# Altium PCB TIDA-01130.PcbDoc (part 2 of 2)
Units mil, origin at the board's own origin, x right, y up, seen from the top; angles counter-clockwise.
Board outline 1055.12 x 1877.5 mil, 6 copper layers (Layer 1 - Top Layer, Layer 2 - GND, Layer 3 - Signal, Layer 4 - Signal, Layer 5 - PWR, Layer 6 - Bottom Layer), stack 66.234 mil thick; 91 components, 54 nets, 295 pads, 113 vias.
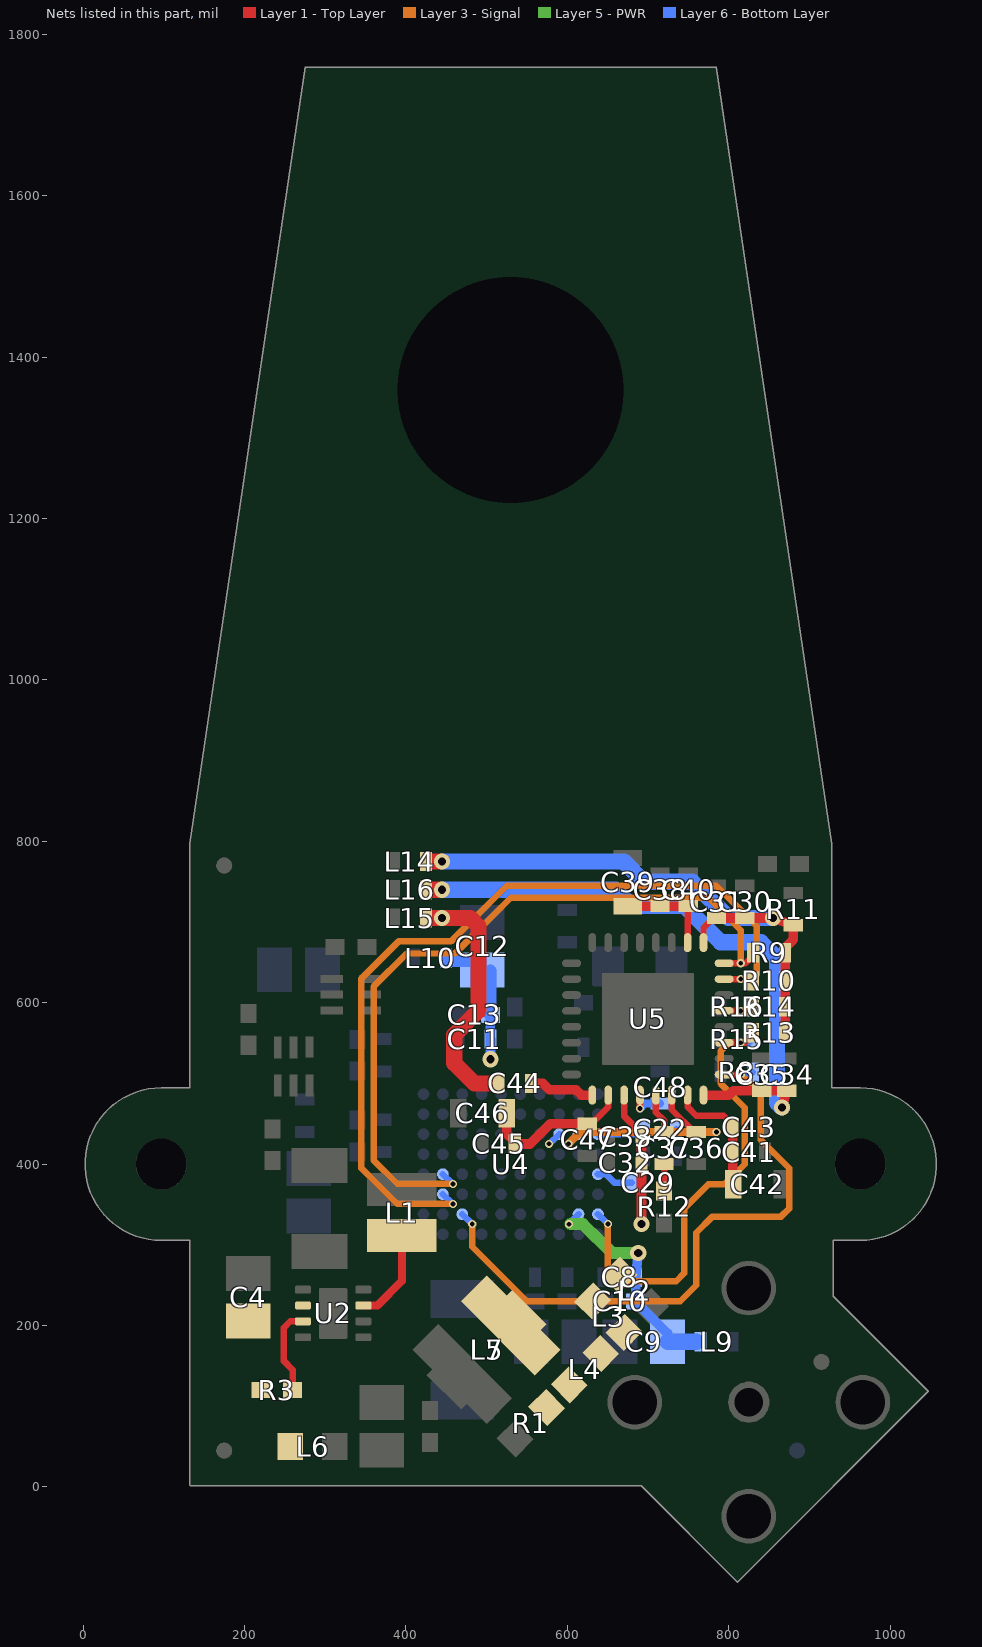
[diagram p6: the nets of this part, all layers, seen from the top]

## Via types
v1: diameter 10, hole 6, Layer 1 - Top Layer to Layer 6 - Bottom Layer, tented both sides, 56 vias
v2: diameter 20, hole 10, Layer 1 - Top Layer to Layer 6 - Bottom Layer, tented both sides, 50 vias
v3: diameter 19.68, hole 7.87, Layer 1 - Top Layer to Layer 6 - Bottom Layer, tented both sides, 7 vias

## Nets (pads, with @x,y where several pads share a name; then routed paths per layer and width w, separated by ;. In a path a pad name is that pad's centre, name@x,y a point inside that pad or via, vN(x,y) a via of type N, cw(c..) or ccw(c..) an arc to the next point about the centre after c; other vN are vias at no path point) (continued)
NetC22_1: C22.1 U4.C1 | length 59.3
  Layer 6 - Bottom Layer w8: U4.C1@638.07,437.2 689.2,437.2 C22.1@695,443
NetC22_2: C22.2 U4.C2 | length 258.1
  Layer 3 - Signal w10: v1(601.65,425.2) 616.46,440 v1(785,440)
  Layer 6 - Bottom Layer w8: v1(601.65,425.2) 602.05,425.2 U4.C2@614.06,437.2 ; C22.2@735,443 738,440 v1(785,440)
NetC29_1: C29.1 U4.E1 | length 46.3
  Layer 6 - Bottom Layer w8: U4.E1@638.07,387.6 648,387.6 658.6,377 C29.1@680,377
NetC36_2: C36.2 U5.14 | length 59.9
  Layer 1 - Top Layer w8: U5.14@729.53,485.51 729.53,467.47 757,440 C36.2@760,440
NetC37_1: C37.1 R12.2 | length 30.3
  Layer 1 - Top Layer w8: R12.2@720,369.69 C37.1@720,400
NetC37_2: C37.2 U5.13 | length 49.7
  Layer 1 - Top Layer w8: U5.13@709.84,485.51 709.84,464.16 720,454 C37.2@720,440
NetC44_2: C44.2 U5.9 | length 75
  Layer 1 - Top Layer w12: C44.2@560,500 570,500 578,492 611,492 617.49,485.51 U5.9@629,485.51
NetC48_1: C48.1 U5.12 | length 43.8
  Layer 1 - Top Layer w8: v1(690.16,469) U5.12@690.16,485.51
  Layer 6 - Bottom Layer w10: v1(690.16,469) 696.16,475 C48.1@715,475
NetL1_1: L1.1 U2.7 | length 116.6
  Layer 1 - Top Layer w10: U2.7@347.4,224.84 364.84,224.84 395.04,255.04 L1.1@395.04,311.46
NetL2_2: L2.2 L3.1
NetL3_2: L3.2 L4.1
NetL4_2: L4.2 L5.2 L7.1 R1.2
NetR3_1: R3.1 U2.3 | length 108.6
  Layer 1 - Top Layer w8: R3.1@259.68,120 259.68,145.32 249,156 249,197.31 256.84,205.16 U2.3@272.6,205.16
NetR14_1: R14.1 R16.2 U5.21 | length 54.8
  Layer 1 - Top Layer w8: U5.21@794.49,589.84 v1(815,589.84) 824.84,589.84 R14.1@830,595
  Layer 6 - Bottom Layer w8: v1(815,589.84) 824.84,589.84 R16.2@830,595
PVDD: C8.1 C9.1 C10.1 L9.2 U4.G2 | length 278.1
  Layer 5 - PWR w15: v1@604,325.59 619.41,325.59 656,290 v2(688,290)
  Layer 6 - Bottom Layer w8: v1(602.05,325.59) 602.05,325.98 U4.G2@614.06,337.99
  Layer 6 - Bottom Layer w12: v2(688,290) C8.1@685,260 685,230.32 C10.1@684.68,230 724.53,190.16 C9.1@724.53,180
  Layer 6 - Bottom Layer w20: C9.1@724.53,180 L9.2@760,180
SCL: R9.1 U4.E9 U5.24 | length 944.1
  Layer 1 - Top Layer w8: U5.24@794.49,648.9 v1(815,648.9) 820.9,648.9 830,658 R9.1@830,662
  Layer 3 - Signal w8: v1@458.07,375.59 389.41,375.59 360,405 360,620 401,661 461,661 530,730 775,730 815,690 v1(815,648.9)
  Layer 6 - Bottom Layer w8: U4.E9@445.94,387.6 457.95,375.59 v1(458.35,375.59)
SDA: R10.1 U4.F9 U5.23 | length 1060.6
  Layer 1 - Top Layer w8: U5.23@794.49,629.21 v1(815,629.21) 829.21,629.21 R10.1@830,630
  Layer 3 - Signal w8: v1(458.35,350.79) 389.21,350.79 345,395 345,630 391,676 456,676 525,745 785,745 835,695 835,635 829.21,629.21 v1(815,629.21)
  Layer 6 - Bottom Layer w8: U4.F9@445.94,362.8 457.95,350.79 v1(458.35,350.79)
SVDD: C11.1 C12.1 C13.1 L10.2 U4.C3 | length 164.1
  Layer 6 - Bottom Layer w8: v1(577.64,425.2) 578.03,425.2 U4.C3@590.04,437.2
  Layer 6 - Bottom Layer w12: C11.1@504.68,555.32 C13.1@504.68,585 ; v2(505,530) C11.1@505,555
  Layer 6 - Bottom Layer w15: L10.2@450,655 453,652 482.84,652 C12.1@484.84,650 ; C13.1@504.68,585 C12.1@504.68,640.16
VCC_PLL: C32.1 C33.1 C44.1 L15.2 U5.11 | length 481.4
  Layer 1 - Top Layer w8: U5.11@670.47,485.51 670.47,459.53 C33.1@690.5,439.5 ; C33.1@690.5,435.5 C33.1@690.5,439.5 ; C33.1@692,433.78 692,438 C33.1@690.5,439.5
  Layer 1 - Top Layer w12: v2(692,326) C32.1@692,402 C33.1@692,433.78
  Layer 1 - Top Layer w20: L15.2@428,705 v2(445,705) 480,705 490,695 490,590 460,560 460,525 485,500 C44.1@510,500
VCC_POC: C4.1 L6.2 R3.2 U2.2
VDD1: C30.1 C31.1 L14.2 R9.2 R10.2 R11.2 R13.2 R14.2 U5.25 | length 729.2
  Layer 1 - Top Layer w8: U5.25@768.9,674.49 768.9,692.9 781,705 C31.1@785,705
  Layer 1 - Top Layer w12: C31.1@785,705 C30.1@820,705 v2(855,705) R11.2@880,696 880,678 870,668 R9.2@870,662 R10.2@870,627 R14.2@870,595 R13.2@870,563
  Layer 1 - Top Layer w20: L14.2@428,775 v2(445,775)
  Layer 6 - Bottom Layer w20: v2(445,775) 670,775 695,750 755,750 800,705 v2(855,705)
VDD1_CAP: C38.1 C39.2 C40.1 U5.26 | length 120.4
  Layer 1 - Top Layer w8: U5.26@749.21,674.49 749.21,719.21 749.53,719.53 C40.1@750,720
  Layer 1 - Top Layer w12: C39.2@675,719.53 C40.1@749.53,719.53
VDDDRV: C34.1 C35.1 L16.2 U5.16 | length 779.8
  Layer 1 - Top Layer w12: U5.16@771,485.51 800.51,485.51 806,491 C35.1@841,491 C34.1@872,491 v2(866,470)
  Layer 1 - Top Layer w20: L16.2@428,740 v2(445,740)
  Layer 6 - Bottom Layer w20: v2(445,740) 660,740 680,720 745,720 790,675 840,675 860,655 860,476 v2(866,470)
VDDDRV_CAP: C41.1 C42.2 C43.1 U5.15 | length 153.5
  Layer 1 - Top Layer w8: U5.15@749.21,485.51 749.21,470.79 760,460 794,460 805,449 C43.1@805,446
  Layer 1 - Top Layer w12: C42.2@805,375 C41.1@805,415 C43.1@805,446
VDDPLL_CAP: C45.1 C46.2 C47.1 U5.10 | length 191.6
  Layer 1 - Top Layer w8: C47.1@625,450 630,450 650.79,470.79 U5.10@650.79,485.51
  Layer 1 - Top Layer w12: C46.2@525,463 525,438 535,428 C45.1@535,425 553.82,425 578.82,450 C47.1@625,450
VSYNC: R8.2 U4.G8 U5.17 | length 779.5
  Layer 1 - Top Layer w8: U5.17@794.49,511.1 v1(815,511.1)
  Layer 3 - Signal w8: v1(482.36,325.98) 482.36,297.64 550,230 740,230 760,250 760,315 780,335 865,335 875,345 875,395 840,430 840,486.1 v1(815,511.1)
  Layer 6 - Bottom Layer w8: U4.G8@469.96,337.99 481.97,325.98 v1(482.36,325.98) ; v1(815,511.1) 826.1,511.1 R8.2@830,514
XCLK: R13.1 R15.2 U4.G1 U5.19 | length 600.3
  Layer 1 - Top Layer w8: U5.19@794.49,550.47 v1(815,550.47) 820.47,550.47 830,560 R13.1@830,563
  Layer 3 - Signal w8: v1(650.47,325.98) 650.47,264.53 660,255 735,255 745,265 745,345 775,375 795,375 820,400 820,470 790,500 790,540 800.47,550.47 v1(815,550.47)
  Layer 6 - Bottom Layer w8: U4.G1@638.07,337.99 650.08,325.98 v1(650.47,325.98) ; v1(815,550.47) 825.47,550.47 R15.2@830,555
pads on no net: FID1.1 FID2.1 FID3.1 FID4.1 FID5.1 FID6.1 LH1.MT1 LH1.MT2 U1.4 U1.5 U3.4 U3.5 U4.A1 U4.A2 U4.A5 U4.A6 U4.A7 U4.A9 U4.A10 U4.B1 U4.B5 U4.B6 U4.B7 U4.B8 U4.B10 U4.C4 U4.C6 U4.C7 U4.C8 U4.C9 U4.C10 U4.D4 U4.D7 U4.D8 U4.E8 U4.F8 U4.G7 U4.G10 U4.H1 U4.H2 U4.H7 U4.H9 U4.H10 U5.20 U5.22

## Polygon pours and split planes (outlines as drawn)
GND on Layer 2 - GND "Layer 2 - GND - GND" (solid, remove dead copper, pour order 16): 810,-140 0,-140 0,802 1050,802 1050,-140
GND on Layer 5 - PWR "Layer 5 - PWR - GND" (solid, remove dead copper, pour order 10): 810,-140 0,-140 0,802 1050,802 1050,-140
3V3 on Layer 5 - PWR "Layer 5 - PWR - 3V3" (solid, remove dead copper, pour order 0): 308.33,477 302.5,477 295,474 295,310 270,285 270,175 300,145 420,145 435,130 645,130 675,160 840,160 850,170 850,185 840,195 660,195 635,170 490,170 335,325 315,345 315,440 315,473
1V3 on Layer 5 - PWR "Layer 5 - PWR - 1V3" (solid, remove dead copper, pour order 2): 170,310 170,330 190,350 240,350 255,365 255,507 272,524 345,524 365,507 365,410 380,395 385,390 390,390 410,390 425,375 425,350 441,334 462,334 464,332.02 464,321 462,319 448.98,319 441,311.02 441,289 475,255 590,255 611,234 629,234 655,260 680,260 715,260 735,280 745,290 745,320 745,350 725,370 655,370 650,375 650,395 650,400 665,415 737,415 790,362 790,300 790,275 765,250 725,210 655,210 630,185 495,185 470,210 430,250 360,320 360,355 360,370 345,385 330,400 330,460 330,485 330,476 316,487.07 306,487.07 297.93,487.07 280,476 280,320 265,305 235,305 220,290 177,290 170,297
1V8 on Layer 5 - PWR "Layer 5 - PWR - 1V8" (solid, remove dead copper, pour order 4): 228,537 242,537 252,537 387,537 445,595 515,595 540,620 540,655 580,695 580,725 565,740 500,740 485,725 485,690 460,665 420,665 395,690 395,740 375,760 215,760 195,740 195,537
GND on Layer 3 - Signal "Layer 3 - Signal - GND" (solid, remove dead copper, pour order 12): 810,-140 0,-140 0,802 1050,802 1050,-140
GND on Layer 4 - Signal "Layer 4 - Signal - GND" (solid, remove dead copper, pour order 14): 810,-140 0,-140 0,802 1050,802 1050,-140
DOVDD on Layer 4 - Signal "Layer 4 - Signal - DOVDD" (solid, remove dead copper, pour order 6): 385,420 390,425 415,425 455,425 465,415 465,400 460,395 445,395 435,385 435,290 445,280 465,260 485,260 490,260 500,270 500,305 505,310 607,310 608,311 608,297 602,291 590,279 590,270 590,250 575,235 450,235 425,260 410,275 410,325 410,370 380,400 380,415 385,420
VCC_PLL on Layer 4 - Signal "Layer 4 - Signal - VCC_PLL" (solid, remove dead copper, pour order 8): 460,700 460,670 440,650 395,650 365,620 365,390 385,370 395,360 395,325 395,265 415,245 440,220 475,220 625,220 645,240 645,295 675,325 682,332 682,338 682,352 695,365 750,365 770,345 775,340 775,300 775,295 755,275 650,170 400,170 370,200 370,275 330,315 270,375 270,435 270,555 300,585 300,625 375,700 390,715 440,715 450,715 460,705
3V3 on Layer 1 - Top Layer "3V3" (solid, remove dead copper, pour order 18): 221,475 221,431 343,431 344,432 344,484 344,494 408,558 408,594 277,594 277,475 223,475 221,477

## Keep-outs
Keep-Out Layer:
  lines w10: 96.88,300.51 ccw(c96.93,305.51) 96.93,300.51 ; 96.88,300.51 cw(c96.93,400) 96.88,499.49 ; 96.88,300.51 ccw(c96.93,400) 96.93,300.51 ; 96.88,499.49 cw(c96.93,400) 96.93,499.49 ; 96.88,499.49 cw(c96.93,494.49) 96.93,499.49 ; 96.88,499.49 cw(c96.93,494.49) 96.93,499.49 ; 96.93,300.51 127.36,300.51 127.36,2.36 ; 96.93,499.49 127.36,499.49 127.36,796.93 ; 127.36,2.36 ccw(c132.36,2.36) 128.83,-1.17 128.84,-1.19 ; 127.36,2.36 ccw(c132.36,2.36) 128.84,-1.19 ; 127.36,796.93 cw(c132.36,797) 127.36,797 ; 127.36,796.93 cw(c132.36,797) 127.36,797 ; 127.36,796.93 127.36,797.07 ; 127.36,797 cw(c132.36,797) 127.36,797.07 ; 127.36,797 127.36,797.64 ; 127.36,797.07 127.36,797.64 ; 127.36,797.64 cw(c132.36,797.64) 127.65,799.31 ; 127.36,797.64 ccw(c132.36,797.64) 127.36,797.64 ; 127.36,797.64 cw(c132.36,797.64) 127.65,799.31 ; 127.65,799.31 270.3,1760.23 ; 128.84,-1.19 129.8,-2.15 ; 129.8,-2.15 ccw(c133.35,1.37) 133.35,-3.63 ; 129.82,-2.17 ccw(c133.35,1.37) 133.35,-3.63 ; 129.8,-2.15 129.82,-2.17 ; 133.35,-3.63 689.56,-3.63 807.45,-121.52 ; 270.3,1760.23 cw(c275.25,1759.5) 275.25,1764.5 ; 270.3,1760.23 cw(c275.25,1759.5) 275.25,1764.5 ; 275.25,1764.5 784.75,1764.5 ; 784.75,1764.5 cw(c784.75,1759.5) 789.7,1760.23 ; 784.75,1764.5 cw(c784.75,1759.5) 789.7,1760.23 ; 789.7,1760.23 932.35,799.31 ; 807.45,-121.52 ccw(c811,-118) 814.54,-121.54 814.55,-121.52 ; 807.45,-121.52 807.46,-121.54 ccw(c811,-118) 814.55,-121.52 ; 814.55,-121.52 1051.02,114.95 ; 932.35,799.31 cw(c927.64,797.64) 932.64,797.64 ; 932.35,799.31 cw(c927.64,797.64) 932.64,797.64 ; 932.64,796.91 ccw(c927.64,797) 932.64,797 ; 932.64,796.91 ccw(c927.64,797) 932.64,797 ; 932.64,796.91 932.64,499.49 963.07,499.49 ; 932.64,796.91 932.64,797.09 ; 932.64,797 ccw(c927.64,797) 932.64,797.01 ; 932.64,797 ccw(c927.64,797) 932.64,797.01 ; 932.64,797.01 ccw(c927.64,797) 932.64,797.09 ; 932.64,797.01 932.64,797.64 ; 932.64,797.09 932.64,797.64 ; 932.64,797.64 ccw(c927.64,797.64) 932.64,797.64 ; 963.07,300.51 ccw(c963.07,305.51) 963.07,300.51 ; 963.07,300.51 ccw(c963.07,305.51) 963.12,300.51 ; 963.07,300.51 ccw(c963.07,305.51) 963.12,300.51 ; 963.07,300.51 ccw(c963.07,400) 963.12,300.51 ; 963.07,300.51 934.63,300.51 934.63,238.44 1051.02,122.05 ; 963.07,499.49 cw(c963.07,494.49) 963.12,499.49 ; 963.07,499.49 ccw(c963.07,494.49) 963.07,499.49 ; 963.07,499.49 cw(c963.07,400) 963.12,499.49 ; 963.07,499.49 cw(c963.07,494.49) 963.12,499.49 ; 963.12,300.51 ccw(c963.07,400) 1062.56,400 ccw(c963.07,400) 963.12,499.49 ; 1051.02,114.95 ccw(c1047.5,118.5) 1052.5,118.5 ; 1051.02,114.95 1051.04,114.96 ccw(c1047.5,118.5) 1052.5,118.5 ; 1051.02,122.05 cw(c1047.5,118.5) 1052.5,118.5 ; 1051.02,122.05 1051.04,122.04 cw(c1047.5,118.5) 1052.5,118.5
  text ".Layer_Name" at 577,-858.49 h60

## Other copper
Layer 1 - Top Layer:
  region net GND: 256,560 256,573 153,573 153,679 326,679 326,651 322,647 294,647 277,630 271.5,624.5 265,610.57 265,531 256,531
  region net 1V3: 247,560 169,560 169,513 210,513 231,526 236,531 247,531
  region net NetL3_2: 671,215 617,161 618,161 640,139 693,192 693,193
  region net NetL2_2: 665,286 608,229 631,206 688,263 688,264 666,286
  region net GND: 384,438 445,438 471,412 503,412 503,453 466,490 391,490 384,483 384,469
  region net GND: 655,750 760,750 775,735 833,735 833,754.63 841,761 861,761 861,790 655,790
  region net GND: 835,456 835,350 876,350 876,394 855,415 855,456 853,458 837,458
  region net GND: 644,446 644,425 637,418 613,418 613,402 620,395 628,395 650,373 650,365 650,343 657,336 673,336 673,377 660,390 660,446
  region net NetL4_2: 500,265 511,265 571,205 591.5,184.5 594.07,178 594.07,167 599.76,151.24 626.5,124.5 576,74 548,102 548,147 465,230
  region net NetC1_1: 405,170 440,205 532,113 532,88 560.5,59.5 524,23 300,23 294,29 294,65 299,70 450,70 460,80 460,104 405,159
  region net VCC_POC: 275,30 268,23 232,23 215,40 215,65 170,110 170,224 176,230 283,230 283,219 244,219 235,210 235,110 275,70
  region net GND: 176,239 170,245 170,281 176,287 206,287 221,315 328,315 329,195 334,191 357,191 359,189 359,173 335,151 335,133 339,130 420,130 440,110 440,80 300,80 285,95 285,151 262,174 262,189 264,191 288,191 292,195 292,235 288,239
  region net NetC5_1: 440,349 436,345 265,345 255,355 251,359 247,359 222,359 222,420 255,420 330,420 358,392 436,392 440,388
  region net 1V8: 374,624 340,624 340,689 326,695 282,695 282,773 303,796 389,796 395,790 395,695 395,655
  text ".Layer_Name" at 577,-858.49 h60
Layer 2 - GND:
  text ".Layer_Name" at 577,-858.49 h60
Layer 5 - PWR:
  region net GND: 590,344.61 590,373 618,401 621,401 627,395 627,391 611,375 611,352 584,325 578,325 578,332.61
  text ".Layer_Name" at 577,-858.49 h60
Layer 3 - Signal:
  text ".Layer_Name" at 577,-858.49 h60
Layer 4 - Signal:
  region net SVDD: 583,423 580,420 551,420 475,496 475,525 490,540 510,540 515,535 515,485 545,455 570,455 583,442
  text ".Layer_Name" at 577,-858.49 h60
Layer 6 - Bottom Layer:
  region net GND: 221,670 153,670 153,586 182,586 211,615 254,615 254,670
  region net GND: 210,300 210,213 234,189 320,189 320,301 308,313 308,358 252,358 252,312 240,300
  region net GND: 414,635 437,635 480,592 480,540 450,540 440,550 440,585 430,595 409,595 409,630
  region net GND: 798,502 644,502 644,610 681,610 690,619 690,662 698,670 765,670 798,637
  region net EVDD: 534,340.4 538.9,345.3 569.1,345.3 574,340.4 574,214 580,208 580,150 570,150 465,150 430,185 430,260 520,260 534,274
  region net GND: 635,290 660,265 660,214 666,208 687,208 691,204 691,149 720,120 720,85 705,70 617,70 587,100 587,267 610,290
  region net GND: 330,530 399.36,530 405,524.36 405,440 330,440
  text ".Layer_Name" at 577,-858.49 h60

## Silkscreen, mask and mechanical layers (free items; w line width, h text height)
Top Overlay:
  rectangle: 627,1151 743,1185
  rectangle: 387,964 617,1019
  lines w7: 665,300 695,300 705,310
  text "ASSY  518670" at 312,1152 h50
  text "PWB    518671 REV B" at 312,1109 h50
  text "LOGIC 518672 REV B" at 312,1064 h50
  text "S/N" at 311,974 h50
  text "TIDA-01130" at 375,640 h40
  text "Rev E3" at 455,605 h40
  text ".Layer_Name" at 577,-858.49 h60
Bottom Overlay:
  lines w7: 685,305 685,290 840,290 840,305 ; 710,250 740,250 755,265 755,290
  lines w10: 195,65 195,735 865,735 865,65 195,65
  text ".Layer_Name" at 577,-858.49 h60
Top Paste:
  text ".Layer_Name" at 577,-858.49 h60
Bottom Paste:
  text ".Layer_Name" at 577,-858.49 h60
Top Solder:
  text ".Layer_Name" at 577,-858.49 h60
  text ".Layer_Name" at 577,-858.49 h60
Bottom Solder:
  text ".Layer_Name" at 577,-858.49 h60
Drill Guide:
  text ".Layer_Name" at 577,-858.49 h60
M1 Board Outline:
  lines w10: 132.36,2.36 132.36,305.51 96.93,305.51 cw(c96.93,400) 96.93,494.49 132.36,494.49 132.36,797.64 ; 132.36,797 275.25,1759.5 784.75,1759.5 927.64,797 ; 133.35,1.37 691.63,1.37 811,-118 1047.5,118.5 929.63,236.37 929.63,305.51 963.07,305.51 ccw(c963.07,400) 963.07,494.49 927.64,494.49 927.64,797.64 ; 137,822 164,822 ; 196,822 227.64,822 ; 259.64,822 291.28,822 ; 323.28,822 354.91,822 ; 386.91,822 418.55,822 ; 450.55,822 482.19,822 ; 514.19,822 545.83,822 ; 577.83,822 609.46,822 ; 641.46,822 673.1,822 ; 705.1,822 736.74,822 ; 712,855 712,895 ; 728,861 712,845 694,863 728,863 ; 768.74,822 800.38,822 ; 832.38,822 864.02,822 ; 896.02,822 923,822
  text "V-SCORE" at 366,866 h75
  text ".Layer_Name" at 577,-858.49 h60
M2 Board Dimensions:
  rectangle: 124.5,-410.5 499.5,-285.5
  rectangle: -0.5,-285.5 124.5,-160.5
  lines w7: -0.5,-285.5 999.5,-285.5 ; 124.5,-410.5 124.5,-160.5 ; 249.5,-410.5 249.5,-160.5 ; 499.5,-410.5 499.5,-160.5 ; 749.5,-410.5 749.5,-160.5 ; -0.5,-410.5 -0.5,-160.5 999.5,-160.5 999.5,-410.5 -0.5,-410.5
  lines w10: -40,400 530,400 ; -0.5,-475.5 -0.5,-455.5 ; 59.5,-485.5 -0.5,-465.5 ; 59.5,-445.5 -0.5,-465.5 ; 223.58,-465.5 -0.5,-465.5 ; 530,-170 530,400 ; 530,970 530,400 ; 775.42,-465.5 999.5,-465.5 ; 939.5,-485.5 999.5,-465.5 ; 939.5,-445.5 999.5,-465.5 ; 999.5,-475.5 999.5,-455.5 ; 1100,400 530,400
  text "1000 (mil)" at 233.58,-501.49 h60
  text ".Layer_Name" at 577,-858.49 h60
M3 3D STEP Top:
  text ".Layer_Name" at 577,-858.49 h60
M4 3D STEP Bottom:
  text ".Layer_Name" at 577,-858.49 h60
M5 Assembly Top:
  lines w10: -292,-930.17 6308,-930.17 ; -292,-726.83 6310,-726.83 ; -292,-523.5 -292,-1133.5 3713,-1133.5 6310,-1133.5 6310,-523.5 -291.5,-523.5 -291.5,-1133.5 1284,-1133.5 ; 2173,-1133.5 2173,-523.5 ; 3440,-726.83 3440,-523.5 ; 4280,-726.83 4280,-523.5 ; 4902,-1140 4902,-937.17
  text "COMPONENTS MARKED 'DNP' SHOULD NOT BE POPULATED." at 1153.5,-318.5 h60
  text "ASSEMBLY VARIANT:" at 1153,-434 h60
  text ".VariantName" at 2189,-434 h60
  text "PCB VIEWED FROM TOP SIDE" at -228.5,-655.67 h60
  text "BOARD #:" at 2248,-655.67 h60
  text ".PRJ_Number" at 2793.5,-655.67 h60
  text "REV:" at 3638,-655.67 h60
  text ".PCB_Rev" at 3929.5,-655.67 h60
  text "SVN REV:" at 4476,-655.67 h60
  text ".VersionControl_RevNumber" at 4982,-655.67 h60
  text "IGNORE ->" at -228.5,-858.49 h60
  text "PLOT NAME =" at -228.5,-1064.34 h60
  text ".plot_File_Name" at 577,-1064.34 h60
  text "GENERATED    :" at 2250,-1064.34 h60
  text ".Print_Date" at 3119.5,-1064.34 h60
  text ".Print_Time" at 3848.5,-1064.34 h60
  text "TEXAS INSTRUMENTS" at 5113,-1064.34 h60
M6 Assembly Bottom:
  lines w10: -292.5,-727.33 6309.5,-727.33 ; -290.5,-930.67 6309.5,-930.67 ; 1115.5,-1140.5 1115.5,-937.67 ; 1737.5,-727.33 1737.5,-524 ; 2577.5,-727.33 2577.5,-524 ; 3844.5,-1134 3844.5,-524 ; 4733.5,-1134 6309,-1134 6309,-524 -292.5,-524 -292.5,-1134 2304.5,-1134 6309.5,-1134 6309.5,-524
  text "COMPONENTS MARKED 'DNP' SHOULD NOT BE POPULATED." at 6102,-318 h60
  text ".VariantName" at 5058,-434 h60
  text "ASSEMBLY VARIANT:" at 6097,-434 h60
  text ".VersionControl_RevNumber" at 1035.5,-656.17 h60
  text "SVN REV:" at 1541.5,-656.17 h60
  text ".PCB_Rev" at 2088,-656.17 h60
  text "REV:" at 2379.5,-656.17 h60
  text ".PRJ_Number" at 3224,-656.17 h60
  text "BOARD #:" at 3769.5,-656.17 h60
  text "PCB VIEWED FROM BOTTOM SIDE" at 6246,-656.17 h60
  text "IGNORE ->" at 2547.85,-858.49 h60
  text "TEXAS INSTRUMENTS" at 904.5,-1064.84 h60
  text ".Print_Time" at 2169,-1064.84 h60
  text ".Print_Date" at 2898,-1064.84 h60
  text "GENERATED    :" at 3767.5,-1064.84 h60
  text ".plot_File_Name" at 5440.5,-1064.84 h60
  text "PLOT NAME =" at 6246,-1064.84 h60
M9 Title Sheet:
  drawing of 1178 lines, arcs and shapes, not listed
  text "1" at 739.84,8036.5 h70
  text "2" at 3235.5,8036.5 h70
  text "3" at 5724.84,8036.5 h70
  text "4" at 8231.51,8036.5 h70
  text "5" at 10730.5,8036.5 h70
  text "6" at 13235.5,8036.5 h70
  text "A" at -416.5,6893.5 h70
  text "A" at 14383.5,6893.5 h70
  text "B" at -416.5,4513.5 h70
  text "B" at 14383.5,4513.5 h70
  text "C" at -416.5,2138.5 h70
  text "C" at 14383.5,2138.5 h70
  text "PROJECT TITLE:" at 11343.5,277.5 h45
  text ".PRJ_Title" at 11393.5,144.17 h70
  text "DESIGNED FOR:" at 11343.5,-23.5 h45
  text ".PRJ_Customer" at 11393.5,-163.5 h70
  text "D" at -416.5,-231.5 h70
  text "D" at 14383.5,-231.5 h70
  text "FILE NAME:" at 11343.5,-323.5 h45
  text ".PCB_File_Name_No_Path" at 11393.5,-443.5 h70
  text "Texas Instruments (TI) and/or its licensors do not warrant the accuracy or completeness of this specification" at 6374,-605.34 h45
  text "ENGINEER:" at 11343.5,-613.5 h45
  text "LAYOUT BY:" at 12848.5,-613.5 h45
  text "or any information contained therein. TI and/or its licensors do not warrant that this design will meet" at 6329.01,-718 h45
  text ".PRJ_Engineer" at 11393.5,-768.49 h70
  text "JMM" at 12852,-800 h100
  text "s  o  l  u  t  i  o  n  s" at 13710,-803 h68
  text "the specifications, will be suitable for your application or fit for any particular purpose, or will operate in" at 6329.01,-830.67 h45
  text ".Layer_Name" at 577,-858.49 h60
  text "ALTIUM DESIGNER VERSION:" at 12848.5,-923.5 h45
  text "an implementation. TI and/or its licensors do not warrant that the design is production worthy. You should" at 6329.01,-943.33 h45
  text "completely validate and test your design implementation to confirm the system functionality for your application." at 6374,-1056 h45
  text ".print_Scale" at 11393.5,-1056.83 h70
  text ".Application_BuildNumber" at 12899,-1056.83 h70
  text "1" at 739.84,-1263.5 h70
  text "2" at 3235.5,-1263.5 h70
  text "3" at 5724.84,-1263.5 h70
  text "4" at 8231.51,-1263.5 h70
  text "5" at 10730.5,-1263.5 h70
  text "6" at 13235.5,-1263.5 h70
M10 Fab Notes:
  drawing of 212 lines, arcs and shapes, not listed
  text "DESIGN INFORMATION" at 12381.02,6810 h60
  text "(REFER ALSO ARRAY/PANEL PROFILING INFORMATION)" at 12019.46,6648.29 h60
  text "BOARD SIZE" at 11333.46,6644 h60
  text "795.28MIL" at 11795.78,6516.18 h60
  text "X" at 12301.46,6516.18 h60
  text "795.28MIL" at 12532.78,6516.18 h60
  text "Number of Layers :" at 11736.46,6319 h60
  text "6" at 12831.27,6309 h60
  text "MIN. TRACK WIDTH:" at 11736.46,6180 h60
  text "5" at 12832.7,6180 h60
  text "MIL" at 12987.46,6180 h60
  text "MIN. CLEARANCE:" at 11736.46,6048 h60
  text "4" at 12832.7,6048 h60
  text "MIL" at 12987.46,6048 h60
  text "MIN. VIA PAD SIZE:" at 11736.46,5916 h60
  text "10" at 12802.71,5916 h60
  text "MIL" at 12987.46,5916 h60
  text "0.05mm (2MIL)" at 12431.46,5774.29 h60
  text "MINIMUM ANNULAR RING" at 11407.23,5770 h60
  text "EXTERNAL" at 13139.46,5770 h60
  text "PER" at 11607.23,5652 h60
  text "IPC-D-275 CLASS 2 LEVEL C" at 11827.23,5652 h60
  text "MIL, HOLES" at 13315.46,5539.71 h60
  text "+/-" at 12923,5539 h60
  text "+/-" at 13777,5539 h60
  text "REGISTRATION TOLERANCES:" at 11407.23,5534 h60
  text "METAL" at 12607,5534 h60
  text "5" at 13183.2,5534 h60
  text "3" at 14016.2,5534 h60
  text "MIL" at 14132.46,5534 h60
  text "MATERIAL:" at 11332.46,5324.54 h60
  text "FR-4 High Tg" at 12318.9,5184.21 h60
  text "FR-408" at 11753.46,5175.64 h60
  text "X" at 12165.46,5175.64 h60
  text "OTHER" at 13241.46,5175.64 h60
  text "62 MIL (1.6mm) +/-10%" at 12073.56,5012.92 h60
  text "THICKNESS:" at 11407.23,5008.64 h60
  text "X" at 11945.4,5008.64 h60
  text "OTHER" at 13358.46,5008.64 h60
  text "TOLERANCE:" at 11407.23,4850.64 h60
  text "X" at 12246.53,4850.64 h60
  text "ANSI IPC-6012 TYPE 3 CLASS 2" at 12433.48,4850.64 h60
  text "OTHER +/-" at 12433.46,4694.64 h60
  text "BOW & TWIST:" at 11407.23,4537.64 h60
  text "X" at 12246.53,4537.64 h60
  text "ANSI IPC-6012 TYPE 3 CLASS 2" at 12433.48,4537.64 h60
  text "OTHER +/-" at 12433.46,4379.13 h60
  text "COPPER THICKNESS (FINISHED):" at 11332.46,4243.64 h60
  text "1.4MIL (1oz)" at 12212.46,4090.92 h60
  text "2MIL (1.4oz)" at 12979.46,4090.92 h60
  text "2.8MIL (2oz)" at 13706.46,4090.92 h60
  text "OUTER:" at 11689.46,4086.64 h60
  text "X" at 12084,4086 h60
  text "1.4MIL (1oz)" at 12212.46,3933.92 h60
  text "2.8MIL (2oz)" at 12979.46,3933.92 h60
  text "N/A" at 13706,3934.29 h60
  text "INNER SIGNAL:" at 11400.38,3929.64 h60
  text "X" at 12085.42,3929.64 h60
  text "DRILLING:" at 11332.46,3790.64 h60
  text "REFERENCE:" at 11407.23,3673.64 h60
  text "X" at 12055.46,3673.64 h60
  text "AS SHOWN" at 12242.46,3673.64 h60
  text "X" at 12956.46,3673.64 h60
  text "NC_DRILL FILES" at 13093.46,3673.64 h60
  text "PTH MIN COPPER THICKNESS:" at 11407.23,3515.64 h60
  text "X" at 12757.46,3515.64 h60
  text "1MIL" at 12894.46,3515.64 h60
  text "OTHER" at 13391.46,3515.64 h60
  text "BOARD FINISH:" at 11332.46,3356.64 h60
  text "SILKSCREEN:" at 11487.68,3238.64 h60
  text "X" at 12436.46,3238.64 h60
  text "TOP" at 12562.46,3238.64 h60
  text "X" at 12946.46,3238.64 h60
  text "BOTTOM" at 13073.46,3238.64 h60
  text "SILKSCREEN COLOR:" at 11487.68,3071.64 h60
  text "X" at 12435.42,3071.64 h60
  text "WHITE" at 12562.46,3071.64 h60
  text "OTHER" at 13073.46,3071.64 h60
  text "SOLDER RESIST COLOR:" at 11487.68,2901.64 h60
  text "GREEN" at 12182.46,2742.44 h60
  text "BLUE" at 12773.46,2742.44 h60
  text "OTHER" at 13311.46,2742.44 h60
  text "BLACK" at 13793.46,2742.44 h60
  text "X" at 13160,2740 h60
  text "IMMERSION GOLD (ENIG)" at 12393.46,2553.92 h60
  text "ENEPIG" at 13731,2550.64 h60
  text "SURFACE FINISH:" at 11332.46,2549.64 h60
  text "X" at 12206.51,2549.64 h60
  text "IMM. TIN/SILVER OR EQUIV" at 11662,2392.64 h60
  text "OTHER" at 13093.46,2392.64 h60
  text "ARRAY/PANEL:" at 11332.46,2213.64 h60
  text "CUT AND TRIM PER MECH LAYER 1" at 12393.46,2209.35 h60
  text "N.C. ROUTE" at 12393.46,2057.64 h60
  text "X" at 13072.46,2057.64 h60
  text "V. SCORE" at 13259.46,2057.64 h60
  text "CERTIFICATION:" at 11332.46,1920.64 h60
  text "MATERIALS AND WORKMANSHIP FOR ALL PCBS" at 12057.46,1920.64 h60
  text "TO MEET OR EXCEED THE REQUIREMENTS OF:" at 12057.46,1822.64 h60
  text "X" at 11683.96,1686.13 h60
  text "ANSI IPC-A-600F CLASS ->" at 11822.96,1686.13 h60
  text "X" at 13462.02,1686.13 h60
  text "2" at 13580.96,1686.14 h60
  text "1" at 13265.96,1684.64 h60
  text "3" at 13934.96,1684.64 h60
  text "X" at 11686.02,1526.64 h60
  text "UL 94V-0" at 11822.96,1526.64 h60
  text "X" at 12498.02,1526.64 h60
  text "RoHS" at 12634.96,1526.64 h60
  text "OTHER" at 13279.36,1526.64 h60
  text "PER ORDER" at 13676.42,1526.64 h60
  text "ADDITIONAL REQUIREMENTS:" at 11332.46,1385.64 h60
  text "MICROSECTION:" at 11407.23,1270.64 h60
  text "YES" at 12312.96,1270.64 h60
  text "REQUIRED" at 13174.46,1114.49 h60
  text "BARE BOARD ELEC. TEST:" at 11407.23,1111.64 h60
  text "NONE" at 12712.96,1111.64 h60
  text "X" at 13047.46,1111.64 h60
  text "PER ORDER" at 13766.46,1111.64 h60
  text "MANUFACTURER'S UL:" at 11407.23,954.64 h60
  text "RAIL" at 12572.96,950.35 h60
  text "METAL" at 13064.77,950.35 h60
  text "X" at 13440,950 h60
  text "SILK" at 13576.46,950.35 h60
  text ".Layer_Name" at 577,-858.49 h60
M11 Gerber Information:
  lines w10: -292,-930.17 6308,-930.17 ; -292,-726.83 6310,-726.83 ; -292,-523.5 -292,-1133.5 3713,-1133.5 6310,-1133.5 6310,-523.5 -291.5,-523.5 -291.5,-1133.5 1284,-1133.5 ; 2173,-1133.5 2173,-523.5 ; 3440,-726.83 3440,-523.5 ; 4280,-726.83 4280,-523.5 ; 4902,-1140 4902,-937.17
  text "ALL ARTWORK VIEWED FROM TOP SIDE" at -228.5,-655.67 h60
  text "BOARD #:" at 2248,-655.67 h60
  text ".PRJ_Number" at 2793.5,-655.67 h60
  text "REV:" at 3638,-655.67 h60
  text ".PCB_Rev" at 3929.5,-655.67 h60
  text "SVN REV:" at 4476,-655.67 h60
  text ".VersionControl_RevNumber" at 4982,-655.67 h60
  text "LAYER NAME =" at -228.5,-858.49 h60
  text "PLOT NAME =" at -228.5,-1064.34 h60
  text ".plot_File_Name" at 577,-1064.34 h60
  text "GENERATED    :" at 2250,-1064.34 h60
  text ".Print_Date" at 3119.5,-1064.34 h60
  text ".Print_Time" at 3848.5,-1064.34 h60
  text "TEXAS INSTRUMENTS" at 5113,-1064.34 h60
M12 Stackup:
  drawing of 399 lines, arcs and shapes, not listed
  text "Layer" at 6311,7843 h60
  text "Name" at 6720.91,7843 h60
  text "Material" at 8130.5,7843 h60
  text "Thickness" at 8990.27,7843 h60
  text "Constant" at 9640.1,7843 h60
  text "Board Layer Stack" at 10209.97,7843 h60
  text "1" at 6311,7723 h60
  text "Top Overlay" at 6720.91,7723 h60
  text "2" at 6311,7603 h60
  text "Top Solder" at 6720.91,7603 h60
  text "Solder Resist" at 8130.5,7603 h60
  text "0.40mil" at 8990.27,7603 h60
  text "3.5" at 9640.1,7603 h60
  text "3" at 6311,7483 h60
  text "Layer 1 - Top Layer" at 6720.91,7483 h60
  text "Copper" at 8130.5,7483 h60
  text "1.40mil" at 8990.27,7483 h60
  text "4" at 6311,7363 h60
  text "Dielectric 1" at 6720.91,7363 h60
  text "370HR" at 8130.5,7363 h60
  text "12.60mil" at 8990.27,7363 h60
  text "4.2" at 9640.1,7363 h60
  text "5" at 6311,7243 h60
  text "Layer 2 - GND" at 6720.91,7243 h60
  text "Copper" at 8130.5,7243 h60
  text "1.40mil" at 8990.27,7243 h60
  text "6" at 6311,7123 h60
  text "Dielectric 2" at 6720.91,7123 h60
  text "370HR" at 8130.5,7123 h60
  text "8.00mil" at 8990.27,7123 h60
  text "4.2" at 9640.1,7123 h60
  text "7" at 6311,7003 h60
  text "Layer 3 - Signal" at 6720.91,7003 h60
  text "Copper" at 8130.5,7003 h60
  text "1.42mil" at 8990.27,7003 h60
  text "8" at 6311,6883 h60
  text "Dielectric 3" at 6720.91,6883 h60
  text "370HR" at 8130.5,6883 h60
  text "16.60mil" at 8990.27,6883 h60
  text "4.2" at 9640.1,6883 h60
  text "9" at 6311,6763 h60
  text "Layer 4 - Signal" at 6720.91,6763 h60
  text "Copper" at 8130.5,6763 h60
  text "1.42mil" at 8990.27,6763 h60
  text "10" at 6311,6643 h60
  text "Dielectric 4" at 6720.91,6643 h60
  text "370HR" at 8130.5,6643 h60
  text "8.00mil" at 8990.27,6643 h60
  text "4.2" at 9640.1,6643 h60
  text "11" at 6311,6523 h60
  text "Layer 5 - PWR" at 6720.91,6523 h60
  text "Copper" at 8130.5,6523 h60
  text "1.40mil" at 8990.27,6523 h60
  text "12" at 6311,6403 h60
  text "Dielectric 5" at 6720.91,6403 h60
  text "370HR" at 8130.5,6403 h60
  text "12.60mil" at 8990.27,6403 h60
  text "4.2" at 9640.1,6403 h60
  text "13" at 6311,6283 h60
  text "Layer 6 - Bottom Layer" at 6720.91,6283 h60
  text "Copper" at 8130.5,6283 h60
  text "1.40mil" at 8990.27,6283 h60
  text "14" at 6311,6163 h60
  text "Bottom Solder" at 6720.91,6163 h60
  text "Solder Resist" at 8130.5,6163 h60
  text "0.40mil" at 8990.27,6163 h60
  text "3.5" at 9640.1,6163 h60
  text "15" at 6311,6043 h60
  text "Bottom Overlay" at 6720.91,6043 h60
  text ".Layer_Name" at 577,-858.49 h60
M13 Component Bodies Top:
  text ".Layer_Name" at 577,-858.49 h60
M14 Component Bodies Bottom:
  text ".Layer_Name" at 577,-858.49 h60
M15 Courtyards Top:
  text ".Layer_Name" at 577,-858.49 h60
M16 Courtyards Bottom:
  text ".Layer_Name" at 577,-858.49 h60
Drill Drawing:
  circle w10: c1583.72,345.36 r16.58
  circle w10: c1583.72,345.36 r27.63
  lines w10: 1556.09,442.06 1611.34,442.06 1611.34,497.31 1556.09,497.31 1556.09,442.06 ; 1556.09,580.19 1569.9,580.19 1583.72,566.38 1597.53,580.19 1611.34,580.19 1597.53,594 1611.34,607.82 1597.53,607.82 1583.72,621.63 1569.9,607.82 1556.09,607.82 1569.9,594 1556.09,580.19 ; 1556.09,704.51 1569.9,704.51 1569.9,690.7 1597.53,690.7 1597.53,704.51 1611.34,704.51 1611.34,732.14 1597.53,732.14 1597.53,745.95 1569.9,745.95 1569.9,732.14 1556.09,732.14 1556.09,704.51 ; 1556.09,815.02 1583.72,828.83 1611.34,815.02 1597.53,842.64 1611.34,870.27 1583.72,856.46 1556.09,870.27 1569.9,842.64 1556.09,815.02 ; 1556.09,966.96 1583.72,939.34 1611.34,966.96 1583.72,994.59 1556.09,966.96 ; 1556.09,1118.91 1611.34,1118.91 1583.72,1063.66 1556.09,1118.91 ; 1567.14,453.11 1600.29,453.11 1600.29,486.26 1567.14,486.26 1567.14,453.11 ; 1567.14,585.71 1575.43,585.71 1583.72,577.43 1592.01,585.71 1600.29,585.71 1592.01,594 1600.29,602.29 1592.01,602.29 1583.72,610.58 1575.43,602.29 1567.14,602.29 1575.43,594 1567.14,585.71 ; 1567.14,710.03 1575.43,710.03 1575.43,701.75 1592.01,701.75 1592.01,710.03 1600.29,710.03 1600.29,726.61 1592.01,726.61 1592.01,734.9 1575.43,734.9 1575.43,726.61 1567.14,726.61 1567.14,710.03 ; 1567.14,826.07 1583.72,834.35 1600.29,826.07 1592.01,842.64 1600.29,859.22 1583.72,850.93 1567.14,859.22 1575.43,842.64 1567.14,826.07 ; 1567.14,1107.86 1600.29,1107.86 1583.72,1074.71 1567.14,1107.86
  lines w12: 1506,280.44 5206.13,280.44 ; 1506,1150.68 5206.13,1150.68 ; 1843.86,156.12 1843.86,1275 ; 2175.86,156.12 2175.86,1275 ; 2812.43,156.12 2812.43,1275 ; 3071.57,156.12 3071.57,1275 ; 3446.72,156.12 3446.72,1275 ; 4639.7,156.12 4639.7,1275 ; 1506,156.12 5206.13,156.12 5206.13,1275 1506,1275 1506,156.12
  text "Symbol" at 1580.59,1187.98 h72
  text "Quantity" at 1881.16,1187.98 h72
  text "Finished Hole Size" at 2213.16,1187.98 h72
  text "Plated" at 2849.72,1187.98 h72
  text "Hole Type" at 3108.86,1187.98 h72
  text "Drill Layer Pair" at 3484.02,1187.98 h72
  text "Hole Tolerance" at 4676.99,1187.98 h72
  text "2" at 1881.16,1063.66 h60
  text "62.99mil (1.600mm)" at 2213.16,1063.66 h60
  text "NPTH" at 2849.72,1063.66 h60
  text "Round" at 3108.86,1063.66 h60
  text "Layer 1 - Top Layer - Layer 6 - Bottom Layer" at 3484.02,1063.66 h60
  text "1" at 1881.16,939.34 h60
  text "280.00mil (7.112mm)" at 2213.16,939.34 h60
  text "NPTH" at 2849.72,939.34 h60
  text "Round" at 3108.86,939.34 h60
  text "Layer 1 - Top Layer - Layer 6 - Bottom Layer" at 3484.02,939.34 h60
  text "56" at 1881.16,815.02 h60
  text "6.00mil (0.152mm)" at 2213.16,815.02 h60
  text "PTH" at 2849.72,815.02 h60
  text "Round" at 3108.86,815.02 h60
  text "Layer 1 - Top Layer - Layer 6 - Bottom Layer" at 3484.02,815.02 h60
  text "7" at 1881.16,690.7 h60
  text "7.87mil (0.200mm)" at 2213.16,690.7 h60
  text "PTH" at 2849.72,690.7 h60
  text "Round" at 3108.86,690.7 h60
  text "Layer 1 - Top Layer - Layer 6 - Bottom Layer" at 3484.02,690.7 h60
  text "50" at 1881.16,566.38 h60
  text "10.00mil (0.254mm)" at 2213.16,566.38 h60
  text "PTH" at 2849.72,566.38 h60
  text "Round" at 3108.86,566.38 h60
  text "Layer 1 - Top Layer - Layer 6 - Bottom Layer" at 3484.02,566.38 h60
  text "1" at 1881.16,442.06 h60
  text "35.43mil (0.900mm)" at 2213.16,442.06 h60
  text "PTH" at 2849.72,442.06 h60
  text "Round" at 3108.86,442.06 h60
  text "Layer 1 - Top Layer - Layer 6 - Bottom Layer" at 3484.02,442.06 h60
  text "4" at 1881.16,317.74 h60
  text "55.12mil (1.400mm)" at 2213.16,317.74 h60
  text "PTH" at 2849.72,317.74 h60
  text "Round" at 3108.86,317.74 h60
  text "Layer 1 - Top Layer - Layer 6 - Bottom Layer" at 3484.02,317.74 h60
  text "121 Total" at 1881.16,193.42 h60
  text ".Layer_Name" at 577,-858.49 h60
Mechanical 17:
  circle w10: c530,400 r240.16
  circle w10: c530,400 r236.22
  lines w10: 175.67,305.51 140.24,305.51 cw(c140.24,400) 140.24,494.49 175.67,494.49 ; 884.33,305.51 921.71,305.51 ccw(c921.71,400) 921.71,494.49 884.33,494.49 ; 175.67,45.67 884.33,45.67 884.33,754.33 175.67,754.33 175.67,45.67 ; 215.04,85.04 215.04,714.96 844.96,714.96 844.96,85.04 215.04,85.04

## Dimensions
132.36,797.64 to 132.36,2.36 on M2 Board Dimensions
132.36,2.36 to 927.64,2.36 on M2 Board Dimensions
